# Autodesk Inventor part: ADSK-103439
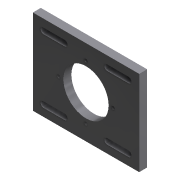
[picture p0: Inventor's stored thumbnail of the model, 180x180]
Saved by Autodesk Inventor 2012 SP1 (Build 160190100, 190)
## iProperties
Shininess: 0.0
Created: 2000-11
Part Number: ADSK-103439
Description: CRS 3/4" THK. x 8" x 10" LONG
Document SubType Name: Modeling
Stock Number: ADSK-103439
Density: 1 g/cm^3
Material: Default
Density: 0.0
Volumn: 0.0
Area: 0.0
PropertySet Name: Model Information
Control State: 0
Master: False
Checked Out: False
Author: gao
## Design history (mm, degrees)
node "Extrusion1" dims "d2" = 19.05, "d3" = 0
  sketch "Sketch1"
    geometry: L1 (-21.637, 179.467)-(232.363, 179.467); L2 (232.363, 179.467)-(232.363, -23.733); L3 (232.363, -23.733)-(-21.637, -23.733); L4 (-21.637, -23.733)-(-21.637, 179.467)
    constraints: 8 end point, 2 parallel, 1 horizontal, 1 perpendicular
    dimensions: "d0" = 203.2 distance of L3.end L1.start; "d1" = 254 distance of L2.end L3.end
node "Hole1" dims "d6" = 107.95, "d7" = 9.525, "d8" = 6.35, "d9" = 60 deg, "d10" = 19.05, "d11" = 118 deg
  sketch "Sketch2"
    geometry: L1 (-21.637, 179.467)-(232.363, 179.467) reference; L2 (-21.637, -23.733)-(-21.637, 179.467) reference; 1 further point
    dimensions: "d4" = 127 distance from line of L2 point (105.363, 77.867) (= 0.5 x d1); "d5" = 101.6 distance from line of L1 point (105.363, 77.867) (= 0.5 x d0)
node "Extrusion2" dims "d17" = 19.05, "d18" = 0
  sketch "Sketch3"
    geometry: L1 (3.763, 147.317)-(54.563, 147.317); L2 (3.763, 160.817)-(54.563, 160.817); C1 r 53.975 at (105.363, 77.867) reference; A1 r 6.75 centre (3.763, 154.067) between (3.763, 160.817) and (3.763, 147.317); A2 r 6.75 centre (54.563, 154.067) between (54.563, 147.317) and (54.563, 160.817)
    constraints: 4 end point, 4 point on circle, 4 tangent, 2 centre point
    dimensions: "d12" = 13.5 diameter of A1; "d13" = 13.5 diameter of A2 (= d12); "d14" = 50.8 distance of A2.centre A1.centre; "d15" = 76.2 vertical distance of C1.centre A2.centre; "d16" = 50.8 horizontal distance of A2.centre C1.centre
node "Rectangular Pattern1" dims "d19" = 20, "d21" = 152.4, "d22" = 20, "d24" = 152.4
node "Hole2" dims "d26" = 7.7978, "d27" = 9.525, "d28" = 6.35, "d29" = 60 deg, "d30" = 19.05, "d31" = 118 deg, "d35" = 12.7
  sketch "Sketch4" dims "d25" = 130.175
    geometry: C1 r 53.975 at (105.363, 77.867) reference; 2 further points
    constraints: 1 coincident, 1 vertical alignment, 2 other
node "Circular Pattern1" dims "d32" = 40, "d34" = 90 deg
body "Solid1"
